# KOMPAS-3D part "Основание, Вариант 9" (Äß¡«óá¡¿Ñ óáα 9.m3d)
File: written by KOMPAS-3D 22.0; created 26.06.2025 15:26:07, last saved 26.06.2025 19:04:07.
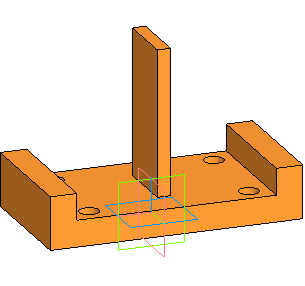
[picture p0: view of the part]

Document properties: Автор: Helen; Полное имя файла: D:\MY\WORK\MPEI\ППЭ_2025-2026\Варианты\Вар 9 СБ\Основание вар 9.m3d

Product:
- Part/product: Основание  | designation Вариант 9
    Масса: 3.93188

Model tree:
1. Эскиз:1
2. Элемент выдавливания:1
     Расстояние 1 = 20
3. Эскиз:3  (with: Элемент выдавливания:1)
4. Элемент выдавливания:3
     Расстояние 2 = 20
5. Массив по сетке:1  (with: Элемент выдавливания:3, Эскиз:3, Элемент выдавливания:1)  (4 pattern instances)
     Шаг 1 = 120; Угол раствора = 90; Шаг 2 = 70
6. Эскиз:4  (with: Элемент выдавливания:1)
7. Элемент выдавливания:4
     Расстояние 1 = 20
8. Зеркальный массив:1
9. Экземпляр ( 1 )
10. Экземпляр ( 2 )  (with: Элемент выдавливания:4)
11. Эскиз:5  (with: Элемент выдавливания:1)
12. Элемент выдавливания:5
     Расстояние 1 = 110

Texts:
  Вариант 9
